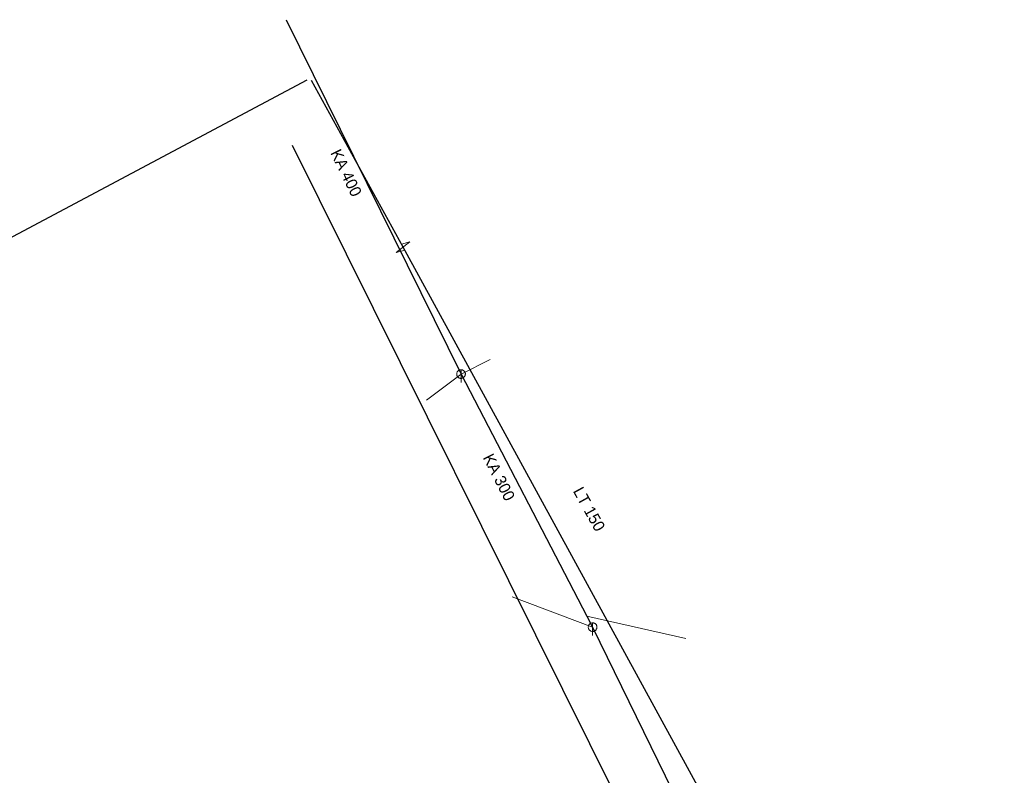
# Model space of a CAD drawing. Extents: x -687468 to -685917, y -974192 to -973456.
# Drawn here: x -686146.9 to -686089.5, y -973580.8 to -973536.7 of the extents above; entities that cross this region are included whole.
import ezdxf
from ezdxf.enums import TextEntityAlignment as Align

# ---------------------------------------------------------------- set-up
doc = ezdxf.new("R2010")
doc.units = 0
doc.header["$LTSCALE"] = 0.27
for name, color, linetype, lineweight in [('1', 7, 'Continuous', 13), ('11', 7, 'Continuous', 13), ('14', 7, 'Continuous', 25), ('17', 7, 'Continuous', 25), ('22', 7, 'Continuous', 13), ('47', 7, 'Continuous', 13)]:
    doc.layers.add(name, color=color, linetype=linetype, lineweight=lineweight)

msp = doc.modelspace()

# ---------------------------------------------------------------- linework, layer by layer
at = {"layer": '11'}
for p, q in [((-686119.437, -973556.504), (-686121.14, -973557.36)), ((-686123.155, -973558.876), (-686121.14, -973557.36)), ((-686118.155, -973570.35), (-686113.469, -973572.12)), ((-686108.028, -973572.785), (-686113.805, -973571.474))]:
    msp.add_line(p, q, dxfattribs=at)
at = {"layer": '14'}
msp.add_line((-686131.329, -973536.69), (-686121.14, -973557.36), dxfattribs=at)
msp.add_lwpolyline([(-686121.14, -973557.36), (-686113.805, -973571.474), (-686113.469, -973572.12), (-686098.62, -973602.51)], dxfattribs=at)
at = {"layer": '17'}
for p, q in [((-686130.129, -973540.219), (-686149.149, -973550.34)), ((-686124.519, -973549.959), (-686129.869, -973540.239)), ((-686130.979, -973544.009), (-686089.459, -973627.585))]:
    msp.add_line(p, q, dxfattribs=at)
msp.add_lwpolyline([(-686092.851, -973610.351), (-686102.274, -973590.875), (-686104.723, -973586.169), (-686124.519, -973549.959)], dxfattribs=at)
at = {"layer": '22'}
for p, q in [((-686121.139, -973557.108), (-686121.14, -973557.852)), ((-686113.468, -973571.868), (-686113.469, -973572.612))]:
    msp.add_line(p, q, dxfattribs=at)
for points in [[(-686120.888, -973557.36), (-686120.889, -973557.334), (-686120.893, -973557.308), (-686120.899, -973557.282), (-686120.909, -973557.258), (-686120.921, -973557.234), (-686120.935, -973557.212), (-686120.952, -973557.191), (-686120.97, -973557.173), (-686120.991, -973557.156), (-686121.013, -973557.142), (-686121.037, -973557.13), (-686121.061, -973557.12), (-686121.087, -973557.114), (-686121.113, -973557.11), (-686121.139, -973557.108), (-686121.165, -973557.109), (-686121.191, -973557.113), (-686121.217, -973557.119), (-686121.242, -973557.129), (-686121.265, -973557.141), (-686121.287, -973557.155), (-686121.308, -973557.172), (-686121.326, -973557.19), (-686121.343, -973557.211), (-686121.357, -973557.233), (-686121.369, -973557.257), (-686121.379, -973557.281), (-686121.386, -973557.307), (-686121.39, -973557.333), (-686121.392, -973557.359), (-686121.391, -973557.385), (-686121.387, -973557.411), (-686121.38, -973557.437), (-686121.37, -973557.462), (-686121.358, -973557.485), (-686121.344, -973557.507), (-686121.327, -973557.528), (-686121.309, -973557.546), (-686121.288, -973557.563), (-686121.266, -973557.577), (-686121.243, -973557.589), (-686121.218, -973557.599), (-686121.192, -973557.606), (-686121.166, -973557.61), (-686121.14, -973557.612), (-686121.114, -973557.611), (-686121.088, -973557.607), (-686121.062, -973557.6), (-686121.038, -973557.59), (-686121.014, -973557.578), (-686120.992, -973557.564), (-686120.971, -973557.547), (-686120.953, -973557.529), (-686120.936, -973557.508), (-686120.922, -973557.486), (-686120.91, -973557.463), (-686120.9, -973557.438), (-686120.894, -973557.412), (-686120.89, -973557.386)], [(-686113.217, -973572.12), (-686113.218, -973572.094), (-686113.222, -973572.068), (-686113.228, -973572.042), (-686113.238, -973572.018), (-686113.25, -973571.994), (-686113.264, -973571.972), (-686113.281, -973571.951), (-686113.299, -973571.933), (-686113.32, -973571.916), (-686113.342, -973571.902), (-686113.366, -973571.89), (-686113.39, -973571.88), (-686113.416, -973571.874), (-686113.442, -973571.87), (-686113.468, -973571.868), (-686113.494, -973571.869), (-686113.52, -973571.873), (-686113.546, -973571.879), (-686113.571, -973571.889), (-686113.594, -973571.901), (-686113.616, -973571.915), (-686113.637, -973571.932), (-686113.655, -973571.95), (-686113.672, -973571.971), (-686113.686, -973571.993), (-686113.698, -973572.017), (-686113.708, -973572.041), (-686113.715, -973572.067), (-686113.719, -973572.093), (-686113.721, -973572.119), (-686113.72, -973572.145), (-686113.716, -973572.171), (-686113.709, -973572.197), (-686113.699, -973572.222), (-686113.687, -973572.245), (-686113.673, -973572.267), (-686113.656, -973572.288), (-686113.638, -973572.306), (-686113.617, -973572.323), (-686113.595, -973572.337), (-686113.572, -973572.349), (-686113.547, -973572.359), (-686113.521, -973572.366), (-686113.495, -973572.37), (-686113.469, -973572.372), (-686113.443, -973572.371), (-686113.417, -973572.367), (-686113.391, -973572.36), (-686113.367, -973572.35), (-686113.343, -973572.338), (-686113.321, -973572.324), (-686113.3, -973572.307), (-686113.282, -973572.289), (-686113.265, -973572.268), (-686113.251, -973572.246), (-686113.239, -973572.223), (-686113.229, -973572.198), (-686113.223, -973572.172), (-686113.219, -973572.146)]]:
    msp.add_lwpolyline(points, close=True, dxfattribs=at)
at = {"layer": '47'}
msp.add_line((-686124.117, -973549.645), (-686124.61, -973549.779), dxfattribs=at)
msp.add_lwpolyline([(-686124.117, -973549.645), (-686124.92, -973550.272), (-686124.427, -973550.138)], dxfattribs=at)

# ---------------------------------------------------------------- texts
at = {"layer": '1'}
for s, rotation, p in [('KA 400', 296, (-686128.137, -973545.769)), ('KA 300', 297, (-686119.221, -973563.527)), ('LT 150', 299, (-686113.958, -973565.395))]:
    msp.add_text(s, height=0.6667, rotation=rotation, dxfattribs=at).set_placement(p, align=Align.CENTER)

doc.saveas('drawing.dxf')
